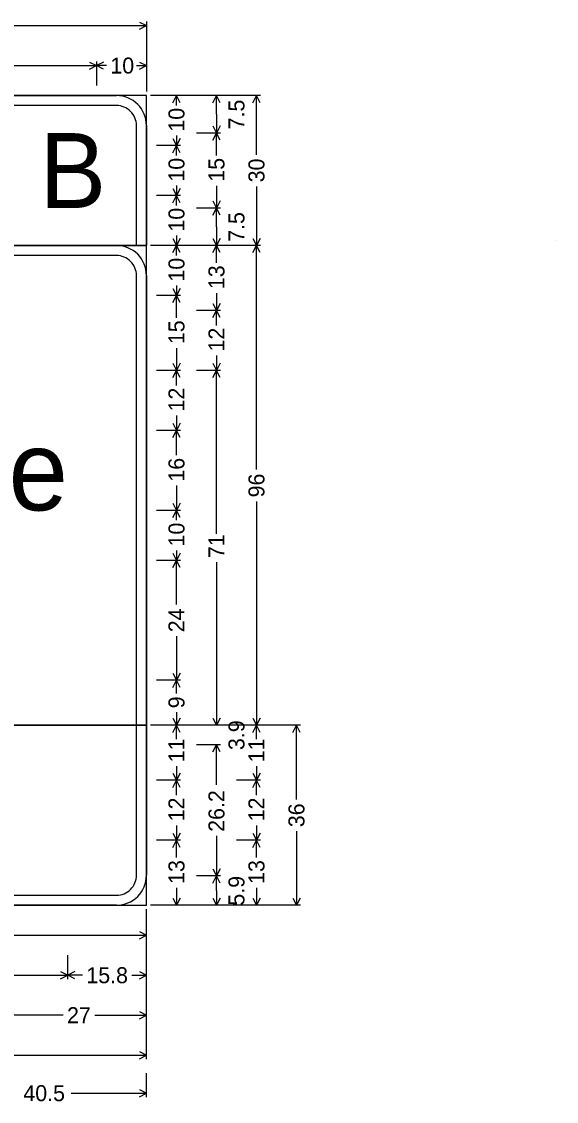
# Model space of a CAD drawing. Extents: x 667331 to 731245, y 738830 to 753817.
# Drawn here: x 723925 to 724085.5, y 746092.8 to 746416.9 of the extents above; entities that cross this region are included whole.
import ezdxf

# ---------------------------------------------------------------- set-up
doc = ezdxf.new("R2010")
doc.units = 0
doc.layers.add('R_SIGN', color=7, linetype='Continuous')

msp = doc.modelspace()

# ---------------------------------------------------------------- linework, layer by layer
at = {"layer": 'R_SIGN'}
for p, q in [((723960.34, 746416.77), (723962.48, 746415.7)), ((723962.48, 746416.9), (723962.48, 746395.9)), ((723874.47, 746415.7), (723962.48, 746415.7)), ((723960.34, 746414.62), (723962.48, 746415.7)), ((723922.6, 746403.7), (723947.48, 746403.7)), ((723945.34, 746404.77), (723947.48, 746403.7)), ((723945.34, 746402.62), (723947.48, 746403.7)), ((723947.48, 746404.9), (723947.48, 746397.7)), ((723947.48, 746404.9), (723947.48, 746397.7)), ((723949.63, 746404.77), (723947.48, 746403.7)), ((723950.45, 746403.7), (723947.48, 746403.7)), ((723949.63, 746402.62), (723947.48, 746403.7)), ((723959.51, 746403.7), (723962.48, 746403.7)), ((723960.34, 746404.77), (723962.48, 746403.7)), ((723960.34, 746402.62), (723962.48, 746403.7)), ((723962.48, 746404.9), (723962.48, 746397.7)), ((723996.68, 746394.7), (723963.68, 746394.7)), ((723972.68, 746394.7), (723965.48, 746394.7)), ((723970.41, 746392.55), (723971.48, 746394.7)), ((723971.48, 746391.73), (723971.48, 746394.7)), ((723972.56, 746392.55), (723971.48, 746394.7)), ((723984.68, 746394.7), (723977.48, 746394.7)), ((723982.41, 746392.55), (723983.48, 746394.7)), ((723983.48, 746389.07), (723983.48, 746394.7)), ((723984.56, 746392.55), (723983.48, 746394.7)), ((723994.41, 746392.55), (723995.48, 746394.7)), ((723995.48, 746376.94), (723995.48, 746394.7)), ((723996.56, 746392.55), (723995.48, 746394.7)), ((723983.48, 746389.07), (723983.48, 746383.45)), ((723982.41, 746385.59), (723983.48, 746383.45)), ((723984.56, 746385.59), (723983.48, 746383.45)), ((723970.41, 746381.84), (723971.48, 746379.7)), ((723971.48, 746382.67), (723971.48, 746379.7)), ((723972.56, 746381.84), (723971.48, 746379.7)), ((723984.68, 746383.45), (723977.48, 746383.45)), ((723982.41, 746381.3), (723983.48, 746383.45)), ((723983.48, 746376.74), (723983.48, 746383.45)), ((723984.56, 746381.3), (723983.48, 746383.45)), ((723972.68, 746379.7), (723965.48, 746379.7)), ((723970.41, 746377.55), (723971.48, 746379.7)), ((723971.48, 746376.73), (723971.48, 746379.7)), ((723972.56, 746377.55), (723971.48, 746379.7)), ((723972.68, 746364.7), (723965.48, 746364.7)), ((723972.68, 746364.7), (723965.48, 746364.7)), ((723970.41, 746366.84), (723971.48, 746364.7)), ((723970.41, 746362.55), (723971.48, 746364.7)), ((723971.48, 746367.67), (723971.48, 746364.7)), ((723972.56, 746366.84), (723971.48, 746364.7)), ((723971.48, 746361.73), (723971.48, 746364.7)), ((723972.56, 746362.55), (723971.48, 746364.7)), ((723983.48, 746367.65), (723983.48, 746360.95)), ((723995.48, 746367.45), (723995.48, 746349.7)), ((723982.41, 746363.09), (723983.48, 746360.95)), ((723984.56, 746363.09), (723983.48, 746360.95)), ((723984.68, 746360.95), (723977.48, 746360.95)), ((723984.68, 746360.95), (723977.48, 746360.95)), ((723982.41, 746358.8), (723983.48, 746360.95)), ((723983.48, 746355.32), (723983.48, 746360.95)), ((723984.56, 746358.8), (723983.48, 746360.95)), ((723983.48, 746355.32), (723983.48, 746349.7)), ((723970.41, 746351.84), (723971.48, 746349.7)), ((723971.48, 746352.67), (723971.48, 746349.7)), ((723972.56, 746351.84), (723971.48, 746349.7)), ((723982.41, 746351.84), (723983.48, 746349.7)), ((723984.56, 746351.84), (723983.48, 746349.7)), ((723994.41, 746351.84), (723995.48, 746349.7)), ((723996.56, 746351.84), (723995.48, 746349.7)), ((723996.68, 746349.7), (723963.68, 746349.7)), ((723996.68, 746349.7), (723963.68, 746349.7)), ((723972.68, 746349.7), (723965.48, 746349.7)), ((723972.68, 746349.7), (723965.48, 746349.7)), ((723970.41, 746347.55), (723971.48, 746349.7)), ((723971.48, 746346.73), (723971.48, 746349.7)), ((723972.56, 746347.55), (723971.48, 746349.7)), ((723984.68, 746349.7), (723977.48, 746349.7)), ((723984.68, 746349.7), (723977.48, 746349.7)), ((723982.41, 746347.55), (723983.48, 746349.7)), ((723983.48, 746344.49), (723983.48, 746349.7)), ((723984.56, 746347.55), (723983.48, 746349.7)), ((723994.41, 746347.55), (723995.48, 746349.7)), ((723995.48, 746282.49), (723995.48, 746349.7)), ((723996.56, 746347.55), (723995.48, 746349.7)), ((724085.48, 746351.2), (724085.48, 746351.2)), ((724085.48, 746351.2), (724085.48, 746351.2)), ((724085.48, 746351.2), (724085.48, 746351.2)), ((724085.48, 746351.2), (724085.48, 746351.2)), ((723970.41, 746336.84), (723971.48, 746334.7)), ((723971.48, 746337.67), (723971.48, 746334.7)), ((723972.56, 746336.84), (723971.48, 746334.7)), ((723983.48, 746335.4), (723983.48, 746330.2)), ((723972.68, 746334.7), (723965.48, 746334.7)), ((723970.41, 746332.55), (723971.48, 746334.7)), ((723971.48, 746327.99), (723971.48, 746334.7)), ((723972.56, 746332.55), (723971.48, 746334.7)), ((723982.41, 746332.34), (723983.48, 746330.2)), ((723984.56, 746332.34), (723983.48, 746330.2)), ((723984.68, 746330.2), (723977.48, 746330.2)), ((723982.41, 746328.05), (723983.48, 746330.2)), ((723983.48, 746325.71), (723983.48, 746330.2)), ((723984.56, 746328.05), (723983.48, 746330.2)), ((723971.48, 746318.9), (723971.48, 746312.2)), ((723983.48, 746316.68), (723983.48, 746312.2)), ((723970.41, 746314.34), (723971.48, 746312.2)), ((723972.56, 746314.34), (723971.48, 746312.2)), ((723982.41, 746314.34), (723983.48, 746312.2)), ((723984.56, 746314.34), (723983.48, 746312.2)), ((723972.68, 746312.2), (723965.48, 746312.2)), ((723970.41, 746310.05), (723971.48, 746312.2)), ((723971.48, 746307.71), (723971.48, 746312.2)), ((723972.56, 746310.05), (723971.48, 746312.2)), ((723984.68, 746312.2), (723977.48, 746312.2)), ((723984.68, 746312.2), (723977.48, 746312.2)), ((723982.41, 746310.05), (723983.48, 746312.2)), ((723983.48, 746263.21), (723983.48, 746312.2)), ((723984.56, 746310.05), (723983.48, 746312.2)), ((723971.48, 746298.68), (723971.48, 746294.2)), ((723972.68, 746294.2), (723965.48, 746294.2)), ((723970.41, 746296.34), (723971.48, 746294.2)), ((723970.41, 746292.05), (723971.48, 746294.2)), ((723972.56, 746296.34), (723971.48, 746294.2)), ((723971.48, 746286.76), (723971.48, 746294.2)), ((723972.56, 746292.05), (723971.48, 746294.2)), ((723971.48, 746277.63), (723971.48, 746270.2)), ((723970.41, 746272.34), (723971.48, 746270.2)), ((723972.56, 746272.34), (723971.48, 746270.2)), ((723995.48, 746272.9), (723995.48, 746205.7)), ((723972.68, 746270.2), (723965.48, 746270.2)), ((723970.41, 746268.05), (723971.48, 746270.2)), ((723971.48, 746267.23), (723971.48, 746270.2)), ((723972.56, 746268.05), (723971.48, 746270.2)), ((723971.48, 746258.17), (723971.48, 746255.2)), ((723972.68, 746255.2), (723965.48, 746255.2)), ((723970.41, 746257.34), (723971.48, 746255.2)), ((723970.41, 746253.05), (723971.48, 746255.2)), ((723972.56, 746257.34), (723971.48, 746255.2)), ((723971.48, 746241.98), (723971.48, 746255.2)), ((723972.56, 746253.05), (723971.48, 746255.2)), ((723983.48, 746254.68), (723983.48, 746205.7)), ((723971.48, 746232.42), (723971.48, 746219.2)), ((723972.68, 746219.2), (723965.48, 746219.2)), ((723972.68, 746219.2), (723965.48, 746219.2)), ((723970.41, 746221.34), (723971.48, 746219.2)), ((723970.41, 746217.05), (723971.48, 746219.2)), ((723972.56, 746221.34), (723971.48, 746219.2)), ((723971.48, 746215.29), (723971.48, 746219.2)), ((723972.56, 746217.05), (723971.48, 746219.2)), ((723971.48, 746209.6), (723971.48, 746205.7)), ((723970.41, 746207.84), (723971.48, 746205.7)), ((723972.56, 746207.84), (723971.48, 746205.7)), ((723982.41, 746207.84), (723983.48, 746205.7)), ((723984.56, 746207.84), (723983.48, 746205.7)), ((723994.41, 746207.84), (723995.48, 746205.7)), ((723996.56, 746207.84), (723995.48, 746205.7)), ((723996.68, 746205.7), (723963.68, 746205.7)), ((724008.68, 746205.7), (723963.68, 746205.7)), ((723972.68, 746205.7), (723965.48, 746205.7)), ((723972.68, 746205.7), (723965.48, 746205.7)), ((723970.41, 746203.55), (723971.48, 746205.7)), ((723971.48, 746201.5), (723971.48, 746205.7)), ((723972.56, 746203.55), (723971.48, 746205.7)), ((723984.68, 746205.7), (723977.48, 746205.7)), ((723984.68, 746205.7), (723977.48, 746205.7)), ((723996.68, 746205.7), (723989.48, 746205.7)), ((723994.41, 746203.55), (723995.48, 746205.7)), ((723995.48, 746201.5), (723995.48, 746205.7)), ((723996.56, 746203.55), (723995.48, 746205.7)), ((724006.41, 746203.55), (724007.48, 746205.7)), ((724007.48, 746183.48), (724007.48, 746205.7)), ((724008.56, 746203.55), (724007.48, 746205.7)), ((723984.68, 746199.89), (723977.48, 746199.89)), ((723982.41, 746197.74), (723983.48, 746199.89)), ((723983.48, 746187.87), (723983.48, 746199.89)), ((723984.56, 746197.74), (723983.48, 746199.89)), ((723971.48, 746193.39), (723971.48, 746189.2)), ((723995.48, 746193.39), (723995.48, 746189.2)), ((723970.41, 746191.34), (723971.48, 746189.2)), ((723972.56, 746191.34), (723971.48, 746189.2)), ((723994.41, 746191.34), (723995.48, 746189.2)), ((723996.56, 746191.34), (723995.48, 746189.2)), ((723972.68, 746189.2), (723965.48, 746189.2)), ((723970.41, 746187.05), (723971.48, 746189.2)), ((723971.48, 746184.71), (723971.48, 746189.2)), ((723972.56, 746187.05), (723971.48, 746189.2)), ((723996.68, 746189.2), (723989.48, 746189.2)), ((723994.41, 746187.05), (723995.48, 746189.2)), ((723995.48, 746184.71), (723995.48, 746189.2)), ((723996.56, 746187.05), (723995.48, 746189.2)), ((723971.48, 746175.68), (723971.48, 746171.2)), ((723995.48, 746175.68), (723995.48, 746171.2)), ((724007.48, 746173.92), (724007.48, 746151.7)), ((723972.68, 746171.2), (723965.48, 746171.2)), ((723972.68, 746171.2), (723965.48, 746171.2)), ((723970.41, 746173.34), (723971.48, 746171.2)), ((723970.41, 746169.05), (723971.48, 746171.2)), ((723972.56, 746173.34), (723971.48, 746171.2)), ((723971.48, 746165.99), (723971.48, 746171.2)), ((723972.56, 746169.05), (723971.48, 746171.2)), ((723983.48, 746172.53), (723983.48, 746160.51)), ((723996.68, 746171.2), (723989.48, 746171.2)), ((723996.68, 746171.2), (723989.48, 746171.2)), ((723994.41, 746173.34), (723995.48, 746171.2)), ((723994.41, 746169.05), (723995.48, 746171.2)), ((723996.56, 746173.34), (723995.48, 746171.2)), ((723995.48, 746165.99), (723995.48, 746171.2)), ((723996.56, 746169.05), (723995.48, 746171.2)), ((723984.68, 746160.51), (723977.48, 746160.51)), ((723984.68, 746160.51), (723977.48, 746160.51)), ((723982.41, 746162.65), (723983.48, 746160.51)), ((723982.41, 746158.36), (723983.48, 746160.51)), ((723984.56, 746162.65), (723983.48, 746160.51)), ((723983.48, 746156.1), (723983.48, 746160.51)), ((723984.56, 746158.36), (723983.48, 746160.51)), ((723971.48, 746156.9), (723971.48, 746151.7)), ((723983.48, 746156.1), (723983.48, 746151.7)), ((723995.48, 746156.9), (723995.48, 746151.7)), ((724008.68, 746151.7), (723963.68, 746151.7)), ((723972.68, 746151.7), (723965.48, 746151.7)), ((723970.41, 746153.84), (723971.48, 746151.7)), ((723972.56, 746153.84), (723971.48, 746151.7)), ((723984.68, 746151.7), (723977.48, 746151.7)), ((723982.41, 746153.84), (723983.48, 746151.7)), ((723984.56, 746153.84), (723983.48, 746151.7)), ((723996.68, 746151.7), (723989.48, 746151.7)), ((723994.41, 746153.84), (723995.48, 746151.7)), ((723996.56, 746153.84), (723995.48, 746151.7)), ((724006.41, 746153.84), (724007.48, 746151.7)), ((724008.56, 746153.84), (724007.48, 746151.7)), ((723962.48, 746105.5), (723962.48, 746150.5)), ((723962.48, 746141.5), (723962.48, 746148.7)), ((723909.75, 746142.7), (723962.48, 746142.7)), ((723960.34, 746143.77), (723962.48, 746142.7)), ((723960.34, 746141.62), (723962.48, 746142.7)), ((723938.86, 746129.5), (723938.86, 746136.7)), ((723938.86, 746129.5), (723938.86, 746136.7)), ((723962.48, 746129.5), (723962.48, 746136.7)), ((723936.71, 746131.77), (723938.86, 746130.7)), ((723941, 746131.77), (723938.86, 746130.7)), ((723960.34, 746131.77), (723962.48, 746130.7)), ((723912.3, 746130.7), (723938.86, 746130.7)), ((723936.71, 746129.62), (723938.86, 746130.7)), ((723943.24, 746130.7), (723938.86, 746130.7)), ((723941, 746129.62), (723938.86, 746130.7)), ((723958.1, 746130.7), (723962.48, 746130.7)), ((723960.34, 746129.62), (723962.48, 746130.7)), ((723962.48, 746117.5), (723962.48, 746124.7)), ((723937.44, 746118.7), (723921.98, 746118.7)), ((723947.03, 746118.7), (723962.48, 746118.7)), ((723960.34, 746119.77), (723962.48, 746118.7)), ((723960.34, 746117.62), (723962.48, 746118.7)), ((723807.24, 746106.7), (723962.48, 746106.7)), ((723960.34, 746107.77), (723962.48, 746106.7)), ((723960.34, 746105.62), (723962.48, 746106.7)), ((723962.48, 746094.1), (723962.48, 746101.3)), ((723960.34, 746096.37), (723962.48, 746095.3)), ((723939.86, 746095.3), (723962.48, 746095.3)), ((723960.34, 746094.22), (723962.48, 746095.3))]:
    msp.add_line(p, q, dxfattribs=at)
for points in [[(723773.48, 746349.7), (723962.48, 746349.7), (723962.48, 746394.7), (723773.48, 746394.7), (723773.48, 746349.7), (723773.48, 746349.7)], [(723782.48, 746394.7), (723953.48, 746394.7)], [(723953.48, 746391.7), (723782.48, 746391.7)], [(723959.48, 746349.7), (723959.48, 746385.7)], [(723962.48, 746385.7), (723962.48, 746349.7)], [(723638.48, 746205.7), (723962.48, 746205.7), (723962.48, 746349.7), (723638.48, 746349.7), (723638.48, 746205.7), (723638.48, 746205.7)], [(723647.48, 746349.7), (723953.48, 746349.7)], [(723953.48, 746346.7), (723647.48, 746346.7)], [(723959.48, 746205.7), (723959.48, 746340.7)], [(723962.48, 746340.7), (723962.48, 746205.7)], [(723638.48, 746151.7), (723962.48, 746151.7), (723962.48, 746205.7), (723638.48, 746205.7), (723638.48, 746151.7), (723638.48, 746151.7)], [(723959.48, 746160.7), (723959.48, 746205.7)], [(723962.48, 746205.7), (723962.48, 746160.7)], [(723647.48, 746154.7), (723953.48, 746154.7)], [(723953.48, 746151.7), (723647.48, 746151.7)]]:
    msp.add_lwpolyline(points, dxfattribs=at)
for centre, radius, start, end in [((723953.48, 746385.7), 9, 0, 90.0002), ((723953.48, 746385.7), 6, 0, 90.0002), ((723953.48, 746340.7), 9, 0, 90.0002), ((723953.48, 746340.7), 6, 0, 90.0002), ((723953.48, 746160.7), 9, 270.0001, 0.0003), ((723953.48, 746160.7), 6, 270.0001, 0.0003)]:
    msp.add_arc(centre, radius, start, end, dxfattribs=at)

# ---------------------------------------------------------------- texts
for s, height, p in [('10', 4.8, (723951.65, 746401.3)), ('B', 22.5, (723930.32, 746360.95)), ('e', 24, (723921.09, 746270.2)), ('15.8', 4.8, (723944.44, 746128.3)), ('27', 4.8, (723938.64, 746116.3)), ('40.5', 4.8, (723925.54, 746092.9))]:
    msp.add_text(s, height=height, dxfattribs=at).set_placement(p)
for s, p in [('10', (723973.88, 746383.87)), ('7.5', (723991.88, 746384.55)), ('10', (723973.88, 746368.87)), ('15', (723985.88, 746368.85)), ('30', (723997.88, 746368.65)), ('10', (723973.88, 746353.87)), ('7.5', (723991.88, 746350.8)), ('10', (723973.88, 746338.87)), ('13', (723985.88, 746336.6)), ('15', (723973.88, 746320.1)), ('12', (723985.88, 746317.88)), ('12', (723973.88, 746299.88)), ('16', (723973.88, 746278.83)), ('96', (723997.88, 746274.1)), ('10', (723973.88, 746259.37)), ('71', (723985.88, 746255.88)), ('24', (723973.88, 746233.62)), ('9', (723973.88, 746210.8)), ('3.9', (723991.88, 746198.27)), ('11', (723973.88, 746194.59)), ('11', (723997.88, 746194.59)), ('12', (723973.88, 746176.88)), ('26.2', (723985.88, 746173.73)), ('12', (723997.88, 746176.88)), ('36', (724009.88, 746175.12)), ('13', (723973.88, 746158.1)), ('13', (723997.88, 746158.1)), ('5.9', (723991.88, 746151.57))]:
    msp.add_text(s, height=4.8, rotation=90.0002, dxfattribs=at).set_placement(p)

doc.saveas('drawing.dxf')
